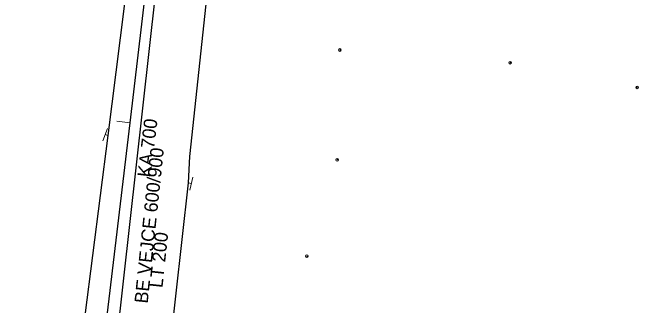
# Model space of a CAD drawing. Extents: x -783064 to -782702, y -1007904 to -1007145.
# Drawn here: x -782795.29 to -782748.5, y -1007458.56 to -1007436.69 of the extents above; entities that cross this region are included whole.
import ezdxf

# ---------------------------------------------------------------- set-up
doc = ezdxf.new("R2010")
doc.units = 0
doc.header["$LTSCALE"] = 0.4
doc.header["$PDMODE"] = 32
doc.header["$PDSIZE"] = 0.2
for name, color, linetype, lineweight in [('1', 7, 'Continuous', 13), ('11', 7, 'Continuous', 13), ('14', 7, 'Continuous', 13), ('17', 7, 'Continuous', 25), ('34', 7, 'Continuous', 13)]:
    doc.layers.add(name, color=color, linetype=linetype, lineweight=lineweight)

msp = doc.modelspace()

# ---------------------------------------------------------------- linework, layer by layer
at = {"layer": '1'}
for p in [(-782770.82, -1007439.489), (-782758.09, -1007440.439), (-782748.6, -1007442.279), (-782771.02, -1007447.689), (-782773.289, -1007454.889)]:
    msp.add_point(p, dxfattribs=at)
at = {"layer": '11'}
msp.add_line((-782787.491, -1007444.808), (-782786.499, -1007444.926), dxfattribs=at)
at = {"layer": '14'}
for p, q in [((-782788.17, -1007445.88), (-782788.359, -1007445.81)), ((-782782.149, -1007449.41), (-782781.93, -1007449.46))]:
    msp.add_line(p, q, dxfattribs=at)
at = {"layer": '14', "lineweight": 25}
for points in [[(-782789.989, -1007474.3), (-782789.55, -1007470.605), (-782788.26, -1007459.742), (-782786.499, -1007444.926), (-782784.094, -1007424.689), (-782783.243, -1007417.342), (-782782.853, -1007416.665)], [(-782789.92, -1007482.8), (-782782.627, -1007417.749), (-782782.853, -1007416.665)]]:
    msp.add_lwpolyline(points, dxfattribs=at)
at = {"layer": '17'}
for points in [[(-782784.199, -1007414.51), (-782788.17, -1007445.88), (-782789.899, -1007459.31), (-782791.09, -1007469.35), (-782793.219, -1007488.27), (-782794.285, -1007499.072), (-782794.78, -1007504.08), (-782795.89, -1007514.14), (-782797.23, -1007526.05), (-782799.52, -1007547.12), (-782801.219, -1007562.54)], [(-782794.527, -1007563.539), (-782793.17, -1007552.95), (-782792.78, -1007548.16), (-782791.739, -1007539.74), (-782790.94, -1007531.25), (-782789.17, -1007514.32), (-782788.309, -1007505.04), (-782787.02, -1007493.25), (-782786.27, -1007487.64), (-782784.98, -1007475.07), (-782783.55, -1007462.11), (-782782.149, -1007449.41), (-782782.032, -1007447.451), (-782779.226, -1007421.176)]]:
    msp.add_lwpolyline(points, dxfattribs=at)
at = {"layer": '34'}
for p, q in [((-782788.531, -1007446.279), (-782788.185, -1007445.341)), ((-782781.819, -1007448.972), (-782782.041, -1007449.947))]:
    msp.add_line(p, q, dxfattribs=at)

# ---------------------------------------------------------------- texts
at = {"layer": '1'}
for s, rotation, p in [('KA 700', 83, (-782784.978, -1007449.035)), ('BE VEJCE 600/900', 84, (-782785.191, -1007458.445)), ('LT 200', 84, (-782784.084, -1007457.282))]:
    msp.add_text(s, height=1, rotation=rotation, dxfattribs=at).set_placement(p)

doc.saveas('drawing.dxf')
